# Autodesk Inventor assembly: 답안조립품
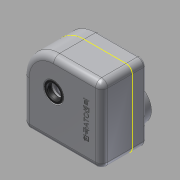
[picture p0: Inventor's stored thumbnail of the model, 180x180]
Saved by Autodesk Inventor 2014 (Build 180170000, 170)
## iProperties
Created: 2015-10
Part Number: 답안조립품
Document SubType Name: Assembly
Designer: youjin16
Author: youjin16
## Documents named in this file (5)
- C:\Users\youjin16\Desktop\451019V1011\답안조립품.iam
- C:\Users\youjin16\Desktop\451019V1011\본체.ipt
- C:\Users\youjin16\Desktop\451019V1011\앞커버.ipt
- C:\Users\youjin16\Desktop\451019V1011\베어링 6002.ipt
- C:\Users\youjin16\Desktop\451019V1011\오일실 15 x 25.ipt
